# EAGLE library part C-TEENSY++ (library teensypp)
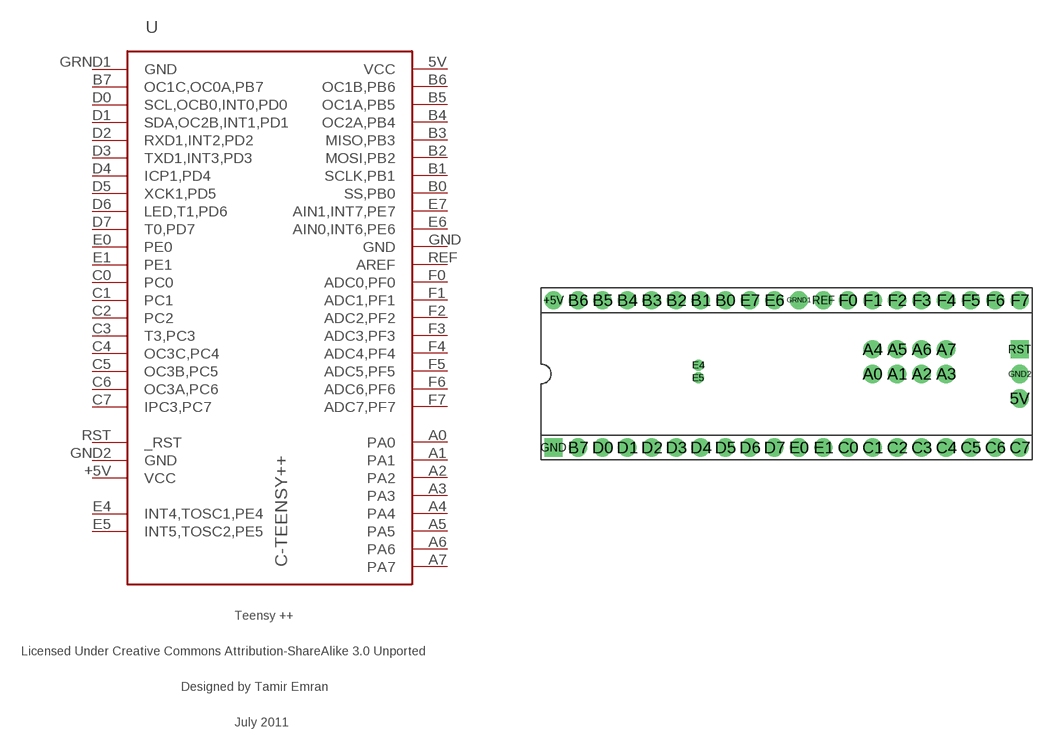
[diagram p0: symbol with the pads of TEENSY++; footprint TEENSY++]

Designator prefix -

## C-TEENSY++  [TEENSY++]
5V  VCC  pwr
+5V  VCC  pwr
A0  PA0
A1  PA1
A2  PA2
A3  PA3
A4  PA4
A5  PA5
A6  PA6
A7  PA7
B0  SS,PB0
B1  SCLK,PB1
B2  MOSI,PB2
B3  MISO,PB3
B4  OC2A,PB4
B5  OC1A,PB5
B6  OC1B,PB6
B7  OC1C,OC0A,PB7
C0  PC0
C1  PC1
C2  PC2
C3  T3,PC3
C4  OC3C,PC4
C5  OC3B,PC5
C6  OC3A,PC6
C7  IPC3,PC7
D0  SCL,OCB0,INT0,PD0
D1  SDA,OC2B,INT1,PD1
D2  RXD1,INT2,PD2
D3  TXD1,INT3,PD3
D4  ICP1,PD4
D5  XCK1,PD5
D6  LED,T1,PD6
D7  T0,PD7
E0  PE0
E1  PE1
E4  INT4,TOSC1,PE4
E5  INT5,TOSC2,PE5
E6  AIN0,INT6,PE6
E7  AIN1,INT7,PE7
F0  ADC0,PF0
F1  ADC1,PF1
F2  ADC2,PF2
F3  ADC3,PF3
F4  ADC4,PF4
F5  ADC5,PF5
F6  ADC6,PF6
F7  ADC7,PF7
GND  GND  pwr
GND2  GND  pwr
GRND1  GND  pwr
REF  AREF  in
RST  _RST  in

## Footprint TEENSY++ (pad centres in mm)
teensy ++
drill 1.016 pad 1.88 round: 5V 24.13,-2.54; +5V -24.13,7.62; A0 8.89,0; A1 11.43,0; A2 13.97,0; A3 16.51,0; A4 8.89,2.54; A5 11.43,2.54; A6 13.97,2.54; A7 16.51,2.54; B0 -6.35,7.62; B1 -8.89,7.62; B2 -11.43,7.62; B3 -13.97,7.62; B4 -16.51,7.62; B5 -19.05,7.62; B6 -21.59,7.62; B7 -21.59,-7.62; C0 6.35,-7.62; C1 8.89,-7.62; C2 11.43,-7.62; C3 13.97,-7.62; C4 16.51,-7.62; C5 19.05,-7.62; C6 21.59,-7.62; C7 24.13,-7.62; D0 -19.05,-7.62; D1 -16.51,-7.62; D2 -13.97,-7.62; D3 -11.43,-7.62; D4 -8.89,-7.62; D5 -6.35,-7.62; D6 -3.81,-7.62; D7 -1.27,-7.62; E0 1.27,-7.62; E1 3.81,-7.62; E6 -1.27,7.62; E7 -3.81,7.62; F0 6.35,7.62; F1 8.89,7.62; F2 11.43,7.62; F3 13.97,7.62; F4 16.51,7.62; F5 19.05,7.62; F6 21.59,7.62; F7 24.13,7.62; GND2 24.13,0; GRND1 1.27,7.62; REF 3.81,7.62
drill 0.635 pad 1.067 round: E4 -9.144,0.914; E5 -9.144,-0.406
drill 1.016 pad 1.88 square: GND -24.13,-7.62; RST 24.13,2.54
